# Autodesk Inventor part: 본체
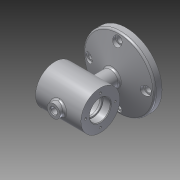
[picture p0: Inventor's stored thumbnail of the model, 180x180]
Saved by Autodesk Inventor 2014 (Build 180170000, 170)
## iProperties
Created: 2018-12
Part Number: 본체
Material: 알루미늄 6061
Document SubType Name: Modeling
Designer: 601-21
Density: 2.71 g/cm^3
Appearance: 알루미늄 - 평지
Mass: 687.571 g
Surface Area: 554.176 cm^2
Volume: 253.716 cm^3
Author: 601-21
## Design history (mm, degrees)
sketch "스케치1"
  geometry: L1 (0, 0)-(-35, 0); L2 (0, 0)-(35, 0); L3 (-35, 0)-(-35, 16); L4 (-35, 16)-(-23.3, 16); L5 (-23, 15.7)-(-23, 14); L6 (-23, 14)-(-20, 14); L7 (-20, 14)-(-20, 22); L8 (-17, 25)-(17, 25); L9 (20, 22)-(20, 14); L10 (20, 14)-(23, 14); L11 (23, 14)-(23, 15.7); L12 (23.3, 16)-(35, 16); L13 (35, 16)-(35, 0); L14 (-35, 16)-(-35, 30); L15 (-35, 30)-(35, 30); L16 (35, 30)-(35, 16); A1 r 3 centre (-17, 22) between (-17, 25) and (-20, 22); A2 r 3 centre (17, 22) between (20, 22) and (17, 25); A3 r 0.3 centre (-23.3, 15.7) between (-23, 15.7) and (-23.3, 16); A4 r 0.3 centre (23.3, 15.7) between (23.3, 16) and (23, 15.7); 4 further points
  constraints: 32 end point, 9 parallel, 9 point on line, 8 point on circle, 8 tangent, 4 centre point, 4 perpendicular, 2 collinear, 2 equal radius, 1 horizontal
  dimensions: "d0" = 35 distance of L1.start L1.end; "d1" = 35 distance of L1.start L2.end; "d2" = 70 distance between parallel lines of L16 L14; "d3" = 12 distance of L3.end point (-23, 16); "d4" = 12 distance of point (23, 16) L12.end; "d5" = 40 distance of point (-20, 25) point (20, 25); "d6" = 3 distance of L5.end L6.end; "d7" = 60 diameter of L15 L1; "d8" = 32 diameter of L4 L1; "d9" = 28 diameter of L6 L1; "d10" = 50 diameter of L8 L1; "d11" = 28 diameter of L10 L2; "d12" = 32 diameter of L12 L2; "d13" = 3 radius of A1; "d14" = 0.3 radius of A3
revolve "회전1" sketch "스케치1" stored, may be unused: angle "d15" = 90 deg
node "작업 평면1"
sketch "스케치2"
  geometry: C1 r 55 at (0, 0); 1 further point
  constraints: 1 centre point, 1 coincident
  dimensions: "d17" = 110 diameter of C1
extrude "돌출1" join sketch "스케치2" distance "d18" = 11; taper "d19" = 0 deg
sketch "스케치3"
  geometry: C1 r 55 at (0, 0) reference; C2 r 12 at (0, 0)
  constraints: 1 centre point, 1 coincident
  dimensions: "d20" = 24 diameter of C2
extrude "돌출2" join sketch "스케치3" stored distance "d21" = 0; taper "d22" = 0 deg
sketch "스케치4"
  geometry: C1 r 55 at (0, 0) reference; C2 r 55 at (0, 0)
  constraints: 1 centre point, 1 coincident, 1 concentric
extrude "돌출3" join sketch "스케치4" distance "d23" = 50; taper "d24" = -75 deg
node "작업 평면2"
sketch "스케치5"
  geometry: L1 (35, -30)-(35, 30) reference; L2 (-35, -30)-(-35, 30) reference; C1 r 10 at (0, 0); 2 further points
  constraints: 1 centre point, 1 coincident, 1 other
  dimensions: "d26" = 20 diameter of C1
extrude "돌출4" join sketch "스케치5" stored distance "d27" = 50; taper "d28" = 0 deg
sketch "스케치6"
  geometry: C1 r 10 at (0, 0) reference; C2 r 5 at (0, 0)
  constraints: 1 centre point, 1 coincident
  dimensions: "d29" = 10 diameter of C2
extrude "돌출5" cut sketch "스케치6" stored distance "d30" = 50; taper "d31" = 0 deg
sketch "스케치7" dims "d32" = 88
  geometry: C1 r 55 at (0, 0) reference; C2 r 4.5 at (-44, 0); 1 further point
  constraints: 1 centre point, 1 coincident, 1 horizontal alignment, 2 other
  dimensions: "d33" = 9 diameter of C2
extrude "돌출6" cut sketch "스케치7" distance "d34" = 10; taper "d35" = 0 deg
node "작업 평면3"
sketch "스케치8"
  geometry: C1 r 4.5 at (-44, 0) reference; C2 r 7 at (-44, 0); 1 further point
  constraints: 1 centre point, 1 coincident
  dimensions: "d37" = 14 diameter of C2
extrude "돌출7" cut sketch "스케치8" distance "d38" = 10; taper "d39" = 0 deg
sketch "스케치9" dims "d43" = 46
  geometry: C1 r 30 at (0, 0) reference; 2 further points
  constraints: 1 coincident, 1 vertical alignment, 2 other
hole "구멍1" sketch "스케치9" at (0, -23) diameter "d44" = 3.242; stored, may be unused: countersink angle "d48" = 90 deg, drill point angle "d50" = 118 deg; dims "d45" = 8, "d46" = 4, "d47" = 2, "d49" = 10
fillet "모깎기1" dims "d54" = 3
chamfer "모따기1" distance "d55" = 1; stored, may be unused: second distance "d56" = 2, angle "d57" = 45 deg
chamfer "모따기2" distance "d58" = 1; stored, may be unused: second distance "d59" = 2, angle "d60" = 45 deg
node "작업 평면4"
sketch "스케치10"
  geometry: L1 (35, -30)-(-35, -30) reference; L2 (35, 30)-(35, -30) reference; L3 (24.887, -3.602)-(-24.887, -3.602); L4 (-24.887, -3.602)-(-24.887, 3.602); L5 (-24.887, 3.602)-(24.887, 3.602); L6 (24.887, 3.602)-(24.887, -3.602); L7 (24.887, -3.602)-(-24.887, 3.602); L8 (-24.887, -3.602)-(24.887, 3.602); 4 further points
  constraints: 4 end point, 2 coincident, 2 midpoint, 2 other
feature "엠보싱1" sketch "스케치10" dims "d61" = 0.5, "d62" = 0
chamfer "모따기3" distance "d63" = 1; stored, may be unused: second distance "d64" = 2, angle "d65" = 45 deg
node "솔리드1"
pattern_circular "원형 패턴1" dims angle "d41" = 360 deg
pattern_circular "원형 패턴2" dims angle "d52" = 360 deg
mirror "대칭1"
node "투영된 루프1"
node "투영된 루프2"
other parameters: "d16" = 75, "d25" = -112
